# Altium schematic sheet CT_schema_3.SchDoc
size 186 x 156 mm
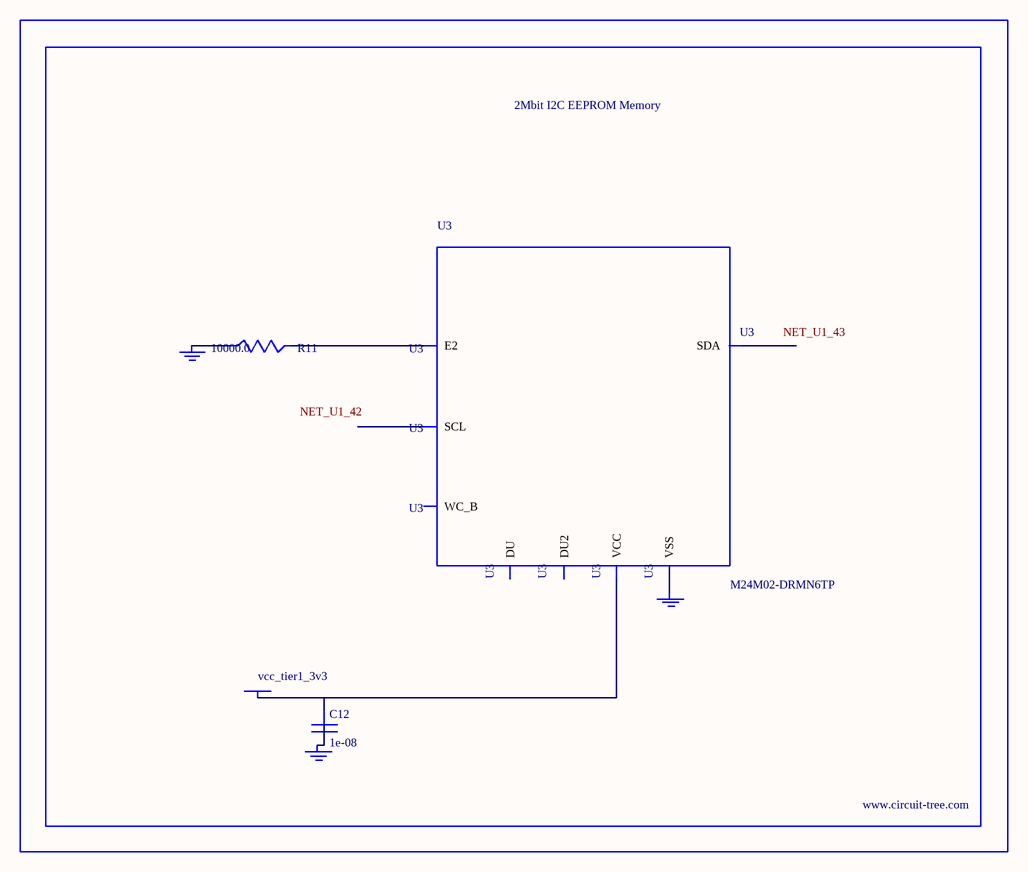
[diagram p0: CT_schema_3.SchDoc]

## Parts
BORDER2  (no value)
C12  1e-08  [C0402]
GND_INSTANCE_2_0  (no value)
GND_INSTANCE_2_1  (no value)
GND_INSTANCE_2_2  (no value)
POWER_INSTANCE_2_0  vcc_tier1_3v3
R11  10000.0  [R0603]
U3  M24M02-DRMN6TP  [SOIC-8]

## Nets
NetC12_1: C12.1 POWER_INSTANCE_2_0.0(PWR) U3.8(VCC)
NetC12_2: C12.2 GND_INSTANCE_2_1.0(GND)
NetGND_INSTANCE_2_0_0: GND_INSTANCE_2_0.0(GND) R11.1
NetGND_INSTANCE_2_2_0: GND_INSTANCE_2_2.0(GND) U3.4(VSS)
NetR11_2: R11.2 U3.3(E2)

Not connected (* = marked no-connect by the designer): U3 1(DU) 2(DU2) 5(SDA) 6(SCL) 7(WC_B)

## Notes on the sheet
- Labels drawn without touching a wire or pin: NET_U1_42, NET_U1_43

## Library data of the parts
BORDER2 = BORDER_PAGE2
C12 = C0402C103K3RAC
GND_INSTANCE_2_0-GND_INSTANCE_2_2 = GND
POWER_INSTANCE_2_0 = PWR
R11 = RC0603JR-0710KL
